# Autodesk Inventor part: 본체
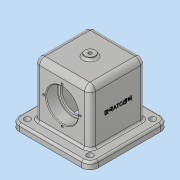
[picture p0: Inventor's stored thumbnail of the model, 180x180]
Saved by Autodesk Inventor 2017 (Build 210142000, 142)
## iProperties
Part Number: 본체
Material: 알루미늄 6061
Document SubType Name: Modeling
Designer: MRC
Density: 2.7 g/cm^3
Appearance: 알루미늄 - 평지
Mass: 1059.83 g
Surface Area: 721.846 cm^2
Volume: 392.53 cm^3
Author: MRC
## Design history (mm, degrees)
sketch "스케치1"
  geometry: L1 (58, -58)-(-58, -58); L2 (-58, -58)-(-58, 58); L3 (-58, 58)-(58, 58); L4 (58, 58)-(58, -58); 3 further points
  constraints: 8 end point, 2 midpoint, 2 parallel, 1 horizontal, 1 horizontal alignment, 1 perpendicular, 1 vertical alignment
  dimensions: "d0" = 116 distance of L3.end L1.start; "d1" = 116 distance of L1.start L1.end
extrude "돌출1" new body sketch "스케치1" distance "d2" = 10; taper "d3" = 0 deg
sketch "스케치2"
  geometry: L1 (-41, 41)-(41, 41); L2 (41, 41)-(41, -41); L3 (41, -41)-(-41, -41); L4 (-41, -41)-(-41, 41); 3 further points
  constraints: 8 end point, 2 midpoint, 2 parallel, 1 horizontal, 1 horizontal alignment, 1 perpendicular, 1 vertical alignment
  dimensions: "d4" = 82 distance of L3.end L1.start; "d5" = 82 distance of L1.start L1.end
extrude "돌출2" join sketch "스케치2" distance "d6" = 80; taper "d7" = 0 deg
sketch "스케치3"
  geometry: L1 (0, 80)-(82, 80) reference; L2 (99, -10)-(-17, -10) reference; C1 r 23.5 at (41, 38); 2 further points
  constraints: 1 centre point, 1 midpoint, 1 vertical alignment
  dimensions: "d8" = 47 diameter of C1; "d9" = 48 distance from line of L2 C1.centre
extrude "돌출3" cut sketch "스케치3" distance "d10" = 17; taper "d11" = 0 deg
sketch "스케치4"
  geometry: L1 (30, 21)-(-30, 21); L2 (-30, 21)-(-30, -21); L3 (-30, -21)-(30, -21); L4 (30, -21)-(30, 21); 3 further points
  constraints: 8 end point, 2 midpoint, 2 parallel, 1 horizontal, 1 horizontal alignment, 1 perpendicular, 1 vertical alignment
  dimensions: "d12" = 42 distance of L3.end L1.start; "d13" = 60 distance of L2.end L3.end
extrude "돌출4" cut sketch "스케치4" distance "d14" = 80; taper "d15" = 0 deg
sketch "스케치6"
  geometry: C1 r 20 at (0, 0); C2 r 23.5 at (0, 0) reference; 1 further point
  constraints: 1 centre point, 1 concentric
  dimensions: "d16" = 40 diameter of C1
extrude "돌출5" cut sketch "스케치6" stored distance "d17" = 80; taper "d18" = 0 deg
node "작업 평면1"
sketch "스케치7"
  geometry: C1 r 7.5 at (0, 0); 1 further point
  constraints: 2 coincident, 1 centre point
  dimensions: "d20" = 15 diameter of C1
extrude "돌출6" join sketch "스케치7" stored distance "d21" = 80; taper "d22" = 0 deg
fillet "모깎기1" dims "d23" = 12
sketch "스케치8"
  geometry: C1 r 4.5 at (46, -46); C2 r 4.5 at (-46, -46); C3 r 4.5 at (-46, 46); C4 r 4.5 at (46, 46); A1 r 12 centre (46, -46) between (46, -58) and (58, -46) reference; A2 r 12 centre (-46, -46) between (-58, -46) and (-46, -58) reference; A3 r 12 centre (-46, 46) between (-46, 58) and (-58, 46) reference; A4 r 12 centre (46, 46) between (58, 46) and (46, 58) reference; 1 further point
  constraints: 4 centre point, 4 coincident
  dimensions: "d24" = 9 diameter of C1; "d25" = 9 diameter of C2; "d26" = 9 diameter of C3; "d27" = 9 diameter of C4
extrude "돌출7" cut sketch "스케치8" stored distance "d28" = 80; taper "d29" = 0 deg
fillet "모깎기2" dims "d30" = 3
sketch "스케치9"
  geometry: L1 (87, -10)-(-5, -10) reference; C1 r 20 at (41, 38) reference; 3 further points
  constraints: 1 midpoint, 1 vertical alignment
  dimensions: "d31" = 27 distance of C1.centre point (41, 65)
hole "구멍1" sketch "스케치9" at (41, 65) diameter "d32" = 3.242; stored, may be unused: countersink angle "d36" = 90 deg, drill point angle "d38" = 118 deg; dims "d33" = 8, "d34" = 4, "d35" = 2, "d37" = 10
sketch "스케치10"
  geometry: 1 further point
hole "구멍2" sketch "스케치10" at (0, 0) diameter "d42" = 4.917; stored, may be unused: countersink angle "d46" = 90 deg, drill point angle "d48" = 118 deg; dims "d43" = 12, "d44" = 4, "d45" = 2, "d47" = 17.1
chamfer "모따기1" distance "d49" = 1; stored, may be unused: second distance "d50" = 2, angle "d51" = 45 deg
fillet "모깎기3" dims "d52" = 3
fillet "모깎기5" dims "d54" = 8
fillet "모깎기6" dims "d55" = 3, "d56" = 8
fillet "모깎기7" dims "d57" = 0.6
fillet "모깎기8" dims "d58" = 3
fillet "모깎기9" dims "d59" = 3
sketch "스케치11"
  geometry: L1 (79, -13)-(-13, -13) reference; 3 further points
  constraints: 1 midpoint, 1 vertical alignment, 1 other
  dimensions: "d60" = 48 distance from line of L1 point (33, 35)
feature "엠보싱1" sketch "스케치11" dims "d0" = 116, "d1" = 116, "d61" = 0.5, "d62" = 0
node "솔리드1"
mirror "미러1"
pattern_circular "원형 패턴1" dims angle "d40" = 360 deg
mirror "미러2"
other parameters: "d19" = 4
